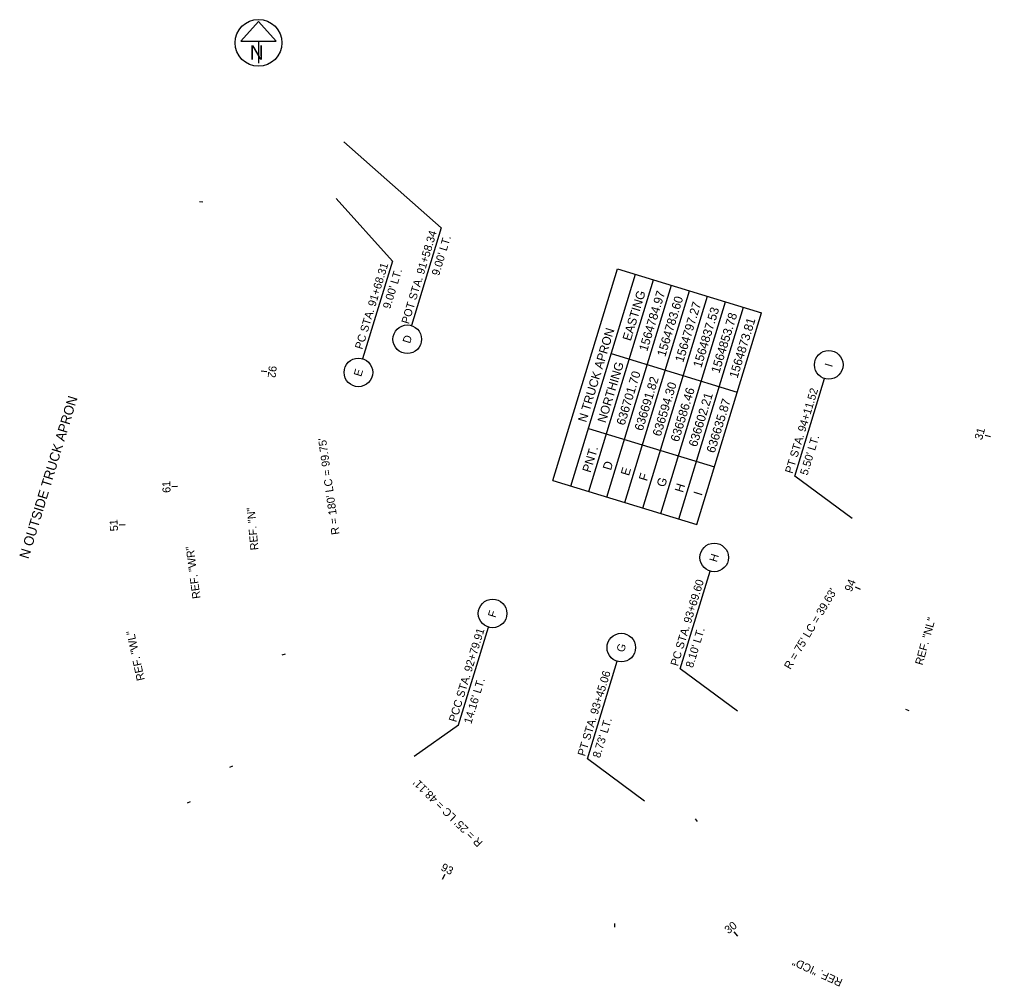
# Model space of a CAD drawing. Extents: x 1564728 to 1564898, y 636554 to 636723.
import ezdxf

# ---------------------------------------------------------------- set-up
doc = ezdxf.new("R2010")
doc.units = 0
for name, color, linetype in [('PV_P_Drive', 7, 'Continuous'), ('SH_Masking', 7, 'Continuous'), ('SH_Text', 7, 'Continuous')]:
    doc.layers.add(name, color=color, linetype=linetype)

msp = doc.modelspace()

# ---------------------------------------------------------------- linework, layer by layer
at = {"layer": 'PV_P_Drive'}
for p, q in [((1564760.28, 636691.15), (1564759.69, 636691.23)), ((1564770.45, 636661.65), (1564771.44, 636661.55)), ((1564898.04, 636650.12), (1564897.08, 636650.39)), ((1564755.87, 636641.43), (1564754.88, 636641.39)), ((1564746.67, 636634.78), (1564745.67, 636634.71)), ((1564875.32, 636623.46), (1564874.4, 636623.84)), ((1564774.13, 636612.03), (1564774.72, 636612.18)), ((1564883.8, 636602.22), (1564883.25, 636602.46)), ((1564765.49, 636592.57), (1564764.92, 636592.36)), ((1564758.07, 636586.33), (1564757.51, 636586.1)), ((1564846.81, 636582.92), (1564846.41, 636583.36)), ((1564802.19, 636572.81), (1564802.63, 636573.7)), ((1564832.25, 636565.05), (1564832.27, 636564.45)), ((1564853.84, 636562.85), (1564853.22, 636563.63))]:
    msp.add_line(p, q, dxfattribs=at)
at = {"layer": 'SH_Masking'}
msp.add_circle((1564770.01, 636719), 4.1, dxfattribs=at)
at = {"layer": 'SH_Text'}
for p, q in [((1564770.01, 636722.73), (1564766.93, 636719.32)), ((1564773.08, 636719.32), (1564770.01, 636722.73)), ((1564766.93, 636719.32), (1564773.08, 636719.32)), ((1564770.01, 636719.32), (1564770.01, 636715.45)), ((1564821.48, 636642.49), (1564832.78, 636679.51)), ((1564824.63, 636641.53), (1564835.93, 636678.55)), ((1564832.78, 636679.51), (1564857.98, 636671.82)), ((1564827.78, 636640.57), (1564839.08, 636677.59)), ((1564830.93, 636639.6), (1564842.23, 636676.62)), ((1564834.08, 636638.64), (1564845.38, 636675.66)), ((1564837.23, 636637.68), (1564848.53, 636674.7)), ((1564840.38, 636636.72), (1564851.68, 636673.74)), ((1564843.53, 636635.76), (1564854.83, 636672.78)), ((1564846.68, 636634.8), (1564857.98, 636671.82)), ((1564831.7, 636664.68), (1564853.75, 636657.95)), ((1564827.71, 636651.61), (1564849.76, 636644.88)), ((1564821.48, 636642.49), (1564846.68, 636634.8))]:
    msp.add_line(p, q, dxfattribs=at)
for points in [[(1564784.96, 636701.7), (1564801.97, 636686.65), (1564796.76, 636669.58)], [(1564783.59, 636691.82), (1564793.42, 636680.85), (1564788.21, 636663.78)], [(1564873.81, 636635.87), (1564863.8, 636643.25), (1564869.01, 636660.32)], [(1564853.78, 636602.21), (1564843.77, 636609.59), (1564848.98, 636626.66)], [(1564797.26, 636594.3), (1564805.01, 636599.8), (1564810.22, 636616.87)], [(1564837.53, 636586.46), (1564827.52, 636593.84), (1564832.73, 636610.91)]]:
    msp.add_lwpolyline(points, dxfattribs=at)
for centre, radius in [((1564770.01, 636719), 4.1), ((1564796.03, 636667.19), 2.5), ((1564869.74, 636662.72), 2.5), ((1564787.48, 636661.39), 2.5), ((1564849.71, 636629.05), 2.5), ((1564810.95, 636619.26), 2.5), ((1564833.46, 636613.3), 2.5)]:
    msp.add_circle(centre, radius, dxfattribs=at)

# ---------------------------------------------------------------- texts
at = {"layer": 'PV_P_Drive'}
for s, rotation, p in [('92', 264.4393, (1564771.82, 636662.61)), ('31', 74.3818, (1564896.54, 636649.49)), ('61', 92.1763, (1564754.64, 636640.37)), ('51', 93.6904, (1564745.46, 636633.69)), ('94', 67.903, (1564873.74, 636622.95)), ('93', 333.4188, (1564801.78, 636574.44)), ('30', 38.4016, (1564852.19, 636563.17))]:
    msp.add_text(s, height=1.4, rotation=rotation, dxfattribs=at).set_placement(p)
at = {"layer": 'SH_Text'}
msp.add_text('N', height=2.5, dxfattribs=at).set_placement((1564768.49, 636716.08))
for s, height, rotation, p in [('POT STA. 91+58.34', 1.4, 73.0287, (1564796.29, 636669.76)), ("9.00' LT.", 1.4, 73.0287, (1564801.58, 636678.2)), ('PC STA. 91+68.31', 1.4, 73.0287, (1564788.16, 636665.33)), ("9.00' LT.", 1.4, 73.0287, (1564793.04, 636672.4)), ('EASTING', 1.54, 73.0287, (1564835.1, 636666.79)), ('1564784.97', 1.54, 73.0287, (1564837.98, 636664.96)), ('1564783.60', 1.54, 73.0287, (1564841.14, 636664.03)), ('1564797.27', 1.54, 73.0287, (1564844.28, 636663.04)), ('1564837.53', 1.54, 73.0287, (1564847.44, 636662.11)), ('1564853.78', 1.54, 73.0287, (1564850.59, 636661.14)), ('1564873.81', 1.54, 73.0287, (1564853.77, 636660.26)), ('N TRUCK APRON', 1.54, 73.0287, (1564827.31, 636652.57)), ('D', 1.4, 73.0287, (1564796.51, 636666.36)), ('NORTHING', 1.54, 73.0287, (1564830.72, 636652.47)), ('I', 1.4, 73.0287, (1564870.32, 636662.23)), ('E', 1.4, 73.0287, (1564787.96, 636660.56)), ('636701.70', 1.54, 73.0287, (1564834.03, 636652.03)), ('636691.82', 1.54, 73.0287, (1564837.19, 636651.07)), ('636594.30', 1.54, 73.0287, (1564840.34, 636650.11)), ('636586.46', 1.54, 73.0287, (1564843.49, 636649.15)), ('PT STA. 94+11.52', 1.4, 73.0287, (1564863.39, 636643.62)), ('N OUTSIDE TRUCK APRON', 1.7, 73.0287, (1564729.77, 636628.7)), ('636602.21', 1.54, 73.0287, (1564846.66, 636648.27)), ('636635.87', 1.54, 73.0287, (1564849.78, 636647.2)), ("R = 180' LC = 99.75'", 1.4, 97.9791, (1564784.18, 636633.12)), ("5.50' LT.", 1.4, 73.0287, (1564866.01, 636643.31)), ('PNT.', 1.54, 73.0287, (1564828.07, 636643.78)), ('D', 1.54, 73.0287, (1564831.64, 636644.18)), ('E', 1.54, 73.0287, (1564834.79, 636643.22)), ('F', 1.54, 73.0287, (1564837.95, 636642.3)), ('G', 1.54, 73.0287, (1564841.07, 636641.24)), ('H', 1.54, 73.0287, (1564844.23, 636640.29)), ('I', 1.54, 73.0287, (1564847.51, 636639.75)), ('REF. "N"', 1.4, 95.1496, (1564770.01, 636630.38)), ('REF. "WR"', 1.4, 97.5429, (1564759.87, 636621.92)), ('H', 1.4, 73.0287, (1564850.16, 636628.14)), ('PC STA. 93+69.60', 1.4, 73.0287, (1564843.35, 636609.96)), ("R = 75' LC = 39.63'", 1.4, 59.2442, (1564863.03, 636609.36)), ('F', 1.4, 73.0287, (1564811.43, 636618.44)), ('REF. "NL"', 1.4, 74.3818, (1564886.14, 636610.13)), ('REF. "WL"', 1.4, 102.3135, (1564750.13, 636607.67)), ('PCC STA. 92+79.91', 1.4, 73.0287, (1564804.59, 636600.17)), ("8.10' LT.", 1.4, 73.0287, (1564845.98, 636609.65)), ('G', 1.4, 73.0287, (1564833.91, 636612.38)), ('PT STA. 93+45.06', 1.4, 73.0287, (1564827.1, 636594.21)), ("14.16' LT.", 1.4, 73.0287, (1564807.22, 636599.86)), ("8.73' LT.", 1.4, 73.0287, (1564829.73, 636593.9)), ("R = 25' LC = 48.11'", 1.4, 135.6269, (1564809.32, 636579.3)), ('REF. "ICD"', 1.4, 155.5722, (1564872.29, 636555.25))]:
    msp.add_text(s, height=height, rotation=rotation, dxfattribs=at).set_placement(p)

doc.saveas('drawing.dxf')
